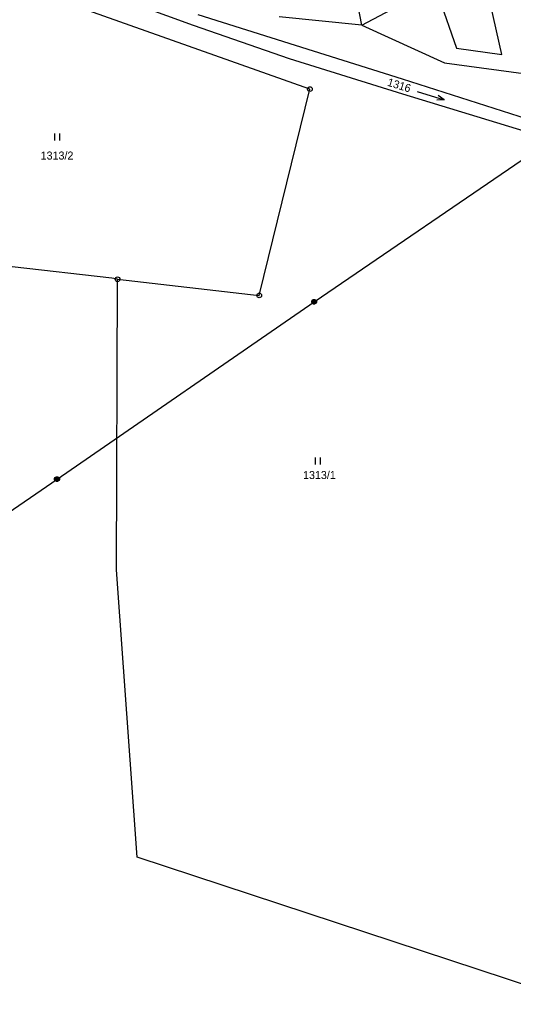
# Model space of a CAD drawing. Extents: x -796130 to -793145, y -1109506 to -1106267.
# Drawn here: x -794609.3 to -794504.5, y -1108039.8 to -1107830.1 of the extents above; entities that cross this region are included whole.
import ezdxf

# ---------------------------------------------------------------- set-up
doc = ezdxf.new("R2010")
doc.units = 0
for name, color, linetype in [('Vrstva 1', 7, 'Continuous'), ('Vrstva 12', 7, 'Continuous'), ('Vrstva 14', 7, 'Continuous'), ('Vrstva 2', 7, 'Continuous'), ('Vrstva 23', 7, 'Continuous'), ('Vrstva 26', 7, 'Continuous'), ('Vrstva 28', 7, 'Continuous')]:
    doc.layers.add(name, color=color, linetype=linetype)

msp = doc.modelspace()

# ---------------------------------------------------------------- linework, layer by layer
at = {"layer": 'Vrstva 1'}
for p, q in [((-794547.69, -1107844.84), (-794607.71, -1107823.54)), ((-794536.65, -1107831.23), (-794538.11, -1107823.72)), ((-794536.65, -1107831.23), (-794521.11, -1107823.01)), ((-794590.18, -1107824.81), (-794572.51, -1107831.27)), ((-794550.76, -1107835.57), (-794571.46, -1107829.04)), ((-794536.65, -1107831.23), (-794554.24, -1107829.51)), ((-794572.51, -1107831.27), (-794552.07, -1107838.32)), ((-794536.65, -1107831.23), (-794519.09, -1107839.24)), ((-794528.05, -1107842.7), (-794550.76, -1107835.57)), ((-794552.07, -1107838.32), (-794528.03, -1107845.84)), ((-794519.09, -1107839.24), (-794492.95, -1107842.79)), ((-794480.34, -1107858.02), (-794528.05, -1107842.7)), ((-794558.44, -1107888.65), (-794547.69, -1107844.84)), ((-794528.03, -1107845.84), (-794481.15, -1107860.19)), ((-794589.78, -1107884.99), (-794610.94, -1107882.54)), ((-794588.55, -1107885.22), (-794589.78, -1107884.99)), ((-794588.77, -1107946.94), (-794588.55, -1107885.22)), ((-794588.55, -1107885.22), (-794558.44, -1107888.65)), ((-794584.35, -1108007.9), (-794588.77, -1107946.94)), ((-794487.55, -1108039.8), (-794584.35, -1108007.9))]:
    msp.add_line(p, q, dxfattribs=at)
at = {"layer": 'Vrstva 12'}
for p, q in [((-794546.81, -1107889.98), (-794489.62, -1107850.92)), ((-794601.41, -1107927.64), (-794546.81, -1107889.98)), ((-794664.83, -1107971.18), (-794601.41, -1107927.64))]:
    msp.add_line(p, q, dxfattribs=at)
at = {"layer": 'Vrstva 2'}
for p, q in [((-794521.11, -1107823.01), (-794516.55, -1107836.12)), ((-794506.91, -1107837.5), (-794509.33, -1107826.78)), ((-794516.55, -1107836.12), (-794506.91, -1107837.5))]:
    msp.add_line(p, q, dxfattribs=at)
at = {"layer": 'Vrstva 23'}
for p, q in [((-794524.898, -1107845.352), (-794519.161, -1107847.107)), ((-794519.161, -1107847.107), (-794520.741, -1107847.146)), ((-794519.161, -1107847.107), (-794520.449, -1107846.19)), ((-794601.88, -1107855.74), (-794601.88, -1107854.24)), ((-794600.88, -1107854.24), (-794600.88, -1107855.74)), ((-794546.53, -1107924.55), (-794546.53, -1107923.05)), ((-794545.53, -1107923.05), (-794545.53, -1107924.55))]:
    msp.add_line(p, q, dxfattribs=at)
at = {"layer": 'Vrstva 26'}
for p, q in [((-794547.31, -1107889.88), (-794547.21, -1107889.68)), ((-794547.31, -1107890.08), (-794547.31, -1107889.88)), ((-794547.21, -1107890.28), (-794547.31, -1107890.08)), ((-794547.21, -1107889.68), (-794547.11, -1107889.58)), ((-794547.11, -1107890.38), (-794547.21, -1107890.28)), ((-794547.11, -1107889.58), (-794546.91, -1107889.48)), ((-794547.11, -1107889.78), (-794547.11, -1107890.18)), ((-794547.11, -1107890.18), (-794546.91, -1107890.28)), ((-794546.91, -1107890.48), (-794547.11, -1107890.38)), ((-794546.91, -1107889.48), (-794546.71, -1107889.48)), ((-794546.91, -1107890.28), (-794546.91, -1107889.68)), ((-794546.91, -1107889.68), (-794546.71, -1107889.68)), ((-794546.71, -1107890.48), (-794546.91, -1107890.48)), ((-794546.71, -1107889.48), (-794546.51, -1107889.58)), ((-794546.71, -1107889.68), (-794546.71, -1107890.28)), ((-794546.71, -1107890.28), (-794546.51, -1107890.18)), ((-794546.51, -1107890.38), (-794546.71, -1107890.48)), ((-794546.51, -1107889.58), (-794546.41, -1107889.68)), ((-794546.51, -1107890.18), (-794546.51, -1107889.78)), ((-794546.41, -1107890.28), (-794546.51, -1107890.38)), ((-794546.41, -1107889.68), (-794546.31, -1107889.88)), ((-794546.31, -1107890.08), (-794546.41, -1107890.28)), ((-794546.31, -1107889.88), (-794546.31, -1107890.08)), ((-794601.91, -1107927.54), (-794601.81, -1107927.34)), ((-794601.91, -1107927.74), (-794601.91, -1107927.54)), ((-794601.81, -1107927.94), (-794601.91, -1107927.74)), ((-794601.81, -1107927.34), (-794601.71, -1107927.24)), ((-794601.71, -1107928.04), (-794601.81, -1107927.94)), ((-794601.71, -1107927.24), (-794601.51, -1107927.14)), ((-794601.71, -1107927.44), (-794601.71, -1107927.84)), ((-794601.71, -1107927.84), (-794601.51, -1107927.94)), ((-794601.51, -1107928.14), (-794601.71, -1107928.04)), ((-794601.51, -1107927.14), (-794601.31, -1107927.14)), ((-794601.51, -1107927.94), (-794601.51, -1107927.34)), ((-794601.51, -1107927.34), (-794601.31, -1107927.34)), ((-794601.31, -1107928.14), (-794601.51, -1107928.14)), ((-794601.31, -1107927.14), (-794601.11, -1107927.24)), ((-794601.31, -1107927.34), (-794601.31, -1107927.94)), ((-794601.31, -1107927.94), (-794601.11, -1107927.84)), ((-794601.11, -1107928.04), (-794601.31, -1107928.14)), ((-794601.11, -1107927.24), (-794601.01, -1107927.34)), ((-794601.11, -1107927.84), (-794601.11, -1107927.44)), ((-794601.01, -1107927.94), (-794601.11, -1107928.04)), ((-794601.01, -1107927.34), (-794600.91, -1107927.54)), ((-794600.91, -1107927.74), (-794601.01, -1107927.94)), ((-794600.91, -1107927.54), (-794600.91, -1107927.74))]:
    msp.add_line(p, q, dxfattribs=at)
at = {"layer": 'Vrstva 28'}
for centre, radius in [((-794547.69, -1107844.84), 0.5), ((-794547.69, -1107844.84), 0.01), ((-794588.55, -1107885.22), 0.5), ((-794588.55, -1107885.22), 0.01), ((-794558.44, -1107888.65), 0.5), ((-794558.44, -1107888.65), 0.01)]:
    msp.add_circle(centre, radius, dxfattribs=at)

# ---------------------------------------------------------------- texts
at = {"layer": 'Vrstva 14'}
msp.add_text('1316', height=1.7, rotation=342.9, dxfattribs=at).set_placement((-794531.392, -1107844.076))
for s, p in [('1313/2', (-794604.886, -1107859.79)), ('1313/1', (-794549.15, -1107927.63))]:
    msp.add_text(s, height=1.7, dxfattribs=at).set_placement(p)

doc.saveas('drawing.dxf')
